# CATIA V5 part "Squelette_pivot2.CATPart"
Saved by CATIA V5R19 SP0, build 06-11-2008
Part number: Squelette_pivot2
Bounding box of the stored display mesh (mm): x 6 to 15, y 0 to 12, z 5 to 15
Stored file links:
  F:\IAO\Catia\Squelette_pivot2.CATPart
  F:\IAO\Catia\Etau.CATProduct
  F:\IAO\Catia\Squelette_barre4.CATPart
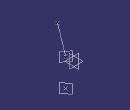
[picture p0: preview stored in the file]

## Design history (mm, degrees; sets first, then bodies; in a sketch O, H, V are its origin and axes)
Set1
  Line1: linked copy from another document
Body1 (main body)
  Point1: type OnCurve, Support Line1, Ratio 0.6
  Point2: (0, 0, 10), relative to Point1
  Plane1: type Normal, Curve Line1, RefPoint Point1
  Point3: (6, 0, 15)
  Line2: type PtPt, SecondPoint Point2, FirstPoint Point3
  Plane2: type Normal, Curve Line2, RefPoint Point2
